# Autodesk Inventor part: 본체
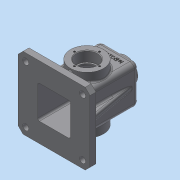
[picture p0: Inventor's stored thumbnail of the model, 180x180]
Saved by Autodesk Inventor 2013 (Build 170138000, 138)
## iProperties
Created: 2018-10
Part Number: 본체
Material: 일반
Document SubType Name: Modeling
Designer: Administrator
Density: 1 g/cm^3
Author: Administrator
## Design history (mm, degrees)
sketch "스케치1"
  geometry: L1 (32.5, 32.5)-(-32.5, 32.5); L2 (-32.5, 32.5)-(-32.5, -32.5); L3 (-32.5, -32.5)-(32.5, -32.5); L4 (32.5, -32.5)-(32.5, 32.5); L5 (32.5, 32.5)-(-32.5, -32.5); L6 (-32.5, 32.5)-(32.5, -32.5); 1 further point
  constraints: 12 end point, 2 midpoint, 2 parallel, 1 horizontal, 1 perpendicular
  dimensions: "d0" = 65 distance of L3.end L2.end; "d1" = 65 distance of L2.end L1.end
extrude "돌출1" new body sketch "스케치1" distance "d2" = 100; taper "d3" = 0 deg
node "작업 평면1"
sketch "스케치3"
  geometry: L1 (60, 60)-(-60, 60); L2 (-60, 60)-(-60, -60); L3 (-60, -60)-(60, -60); L4 (60, -60)-(60, 60); L5 (60, 60)-(-60, -60); L6 (-60, 60)-(60, -60); 3 further points
  constraints: 12 end point, 3 midpoint, 2 parallel, 1 coincident, 1 horizontal, 1 perpendicular
  dimensions: "d5" = 120 distance of L3.end L2.end; "d6" = 120 distance of L2.end L1.end
extrude "돌출2" join sketch "스케치3" distance "d7" = 10; taper "d8" = 0 deg
node "작업 평면2"
sketch "스케치16"
  geometry: C1 r 20 at (0, 0); 1 further point
  constraints: 1 centre point, 1 coincident
  dimensions: "d105" = 40 diameter of C1
extrude "돌출8" join sketch "스케치16" stored distance "d106" = 3; taper "d107" = 7 deg
sketch "스케치5"
  geometry: L1 (0, 0)-(0, -100) reference; L2 (92.5, -110)-(-27.5, -110) reference; C1 r 27.5 at (32.5, -55); 1 further point
  constraints: 1 centre point
  dimensions: "d12" = 55 diameter of C1; "d13" = 55 distance from line of L2 C1.centre; "d14" = 32.5 distance from line of C1.centre L1
extrude "돌출4" join sketch "스케치5" distance "d15" = 15; taper "d16" = 0 deg
sketch "스케치7"
  geometry: L1 (-27.5, -27.5)-(27.5, -27.5); L2 (27.5, -27.5)-(27.5, 27.5); L3 (27.5, 27.5)-(-27.5, 27.5); L4 (-27.5, 27.5)-(-27.5, -27.5); L5 (-27.5, -27.5)-(27.5, 27.5); L6 (27.5, -27.5)-(-27.5, 27.5); 1 further point
  constraints: 12 end point, 2 midpoint, 2 parallel, 1 horizontal, 1 perpendicular
  dimensions: "d17" = 55 distance of L3.end L2.end; "d18" = 55 distance of L2.end L1.end
extrude "돌출5" cut sketch "스케치7" distance "d19" = 105; taper "d20" = 0 deg
sketch "스케치8"
  geometry: C1 r 27.5 at (0, 0) reference; C2 r 17.5 at (0, 0); 1 further point
  constraints: 1 centre point, 1 coincident
  dimensions: "d21" = 35 diameter of C2
extrude "돌출6" cut sketch "스케치8" distance "d22" = 17; taper "d23" = 0 deg
sketch "스케치9"
  geometry: C1 r 17.5 at (0, 0) reference; C2 r 15 at (0, 0); 1 further point
  constraints: 1 centre point, 1 coincident
  dimensions: "d24" = 30 diameter of C2
extrude "돌출7" cut sketch "스케치9" distance "d25" = 3; taper "d26" = 0 deg
chamfer "모따기1" distance "d27" = 1; stored, may be unused: second distance "d28" = 2, angle "d29" = 45 deg
sketch "스케치10"
  geometry: L1 (-60, -100)-(-60, -110) reference; L2 (60, -100)-(-60, -100) reference; L3 (32.5, -100)-(60, -100) reference; L4 (60, -100)-(60, -110) reference; L5 (60, -110)-(27.5, -110) reference; L6 (27.5, -110)-(27.5, -5) reference; L7 (27.5, -5)-(-27.5, -5) reference; L8 (-27.5, -5)-(-27.5, -110) reference; L9 (-27.5, -110)-(-60, -110) reference; L10 (-60, -110)-(-60, -100) reference; L11 (-60, -100)-(-32.5, -100) reference; L12 (-32.5, -100)-(-32.5, 0) reference; L13 (-32.5, 0)-(-21.228, 0) reference; L14 (21.228, 0)-(32.5, 0) reference; L15 (32.5, 0)-(32.5, -100) reference; L16 (-48, -100)-(-38.544, -46.373); L17 (-21.228, 0)-(-20, 10) reference; L18 (-20, 10)-(20, 10) reference; L19 (20, 10)-(21.228, 0) reference; 1 further point
  constraints: 2 end point, 1 point on line
  dimensions: "d36" = 12 distance from line of L1 L16.start; "d37" = 10 deg angle of L1 L16
feature "리브1" sketch "스케치10" dims "d38" = 1, "d39" = 10, "d40" = 0, "d41" = 0, "d42" = 1, "d43" = 1
chamfer "모따기2" distance "d44" = 8; stored, may be unused: second distance "d45" = 2, angle "d46" = 45 deg
sketch "스케치12"
  geometry: L1 (-40, 27.5)-(-40, 30.5) reference; L2 (-40, 30.5)-(-37.5, 30.5) reference; L3 (-37.5, 30.5)-(-37.5, 46.5) reference; L4 (-37.5, 46.5)-(-36.5, 47.5) reference; L5 (-36.5, 47.5)-(-27.5, 47.5) reference; L6 (-27.5, 47.5)-(-27.5, 32.5) reference; L7 (-27.5, 32.5)-(0, 32.5) reference; L8 (0, 32.5)-(0, 21.228) reference; L9 (0, -21.228)-(0, -32.5) reference; L10 (0, -32.5)-(-27.5, -32.5) reference; L11 (-82.5, -47.5)-(-82.5, -32.5) reference; L12 (-72.5, -47.5)-(-82.5, -47.5) reference; L13 (-72.5, -30.5)-(-72.5, -47.5) reference; L14 (-37.5, -47.5)-(-37.5, -30.5) reference; L15 (-27.5, -47.5)-(-37.5, -47.5) reference; L16 (-27.5, -32.5)-(-27.5, -47.5) reference; L17 (-82.5, -32.5)-(-100, -32.5) reference; L18 (-100, -32.5)-(-100, -60) reference; L19 (-100, -60)-(-110, -60) reference; L20 (-110, -60)-(-110, -27.5) reference; L21 (-110, -27.5)-(-70, -27.5) reference; L22 (-5, -27.5)-(-5, 27.5) reference; L23 (-5, 27.5)-(-40, 27.5) reference; L24 (-70, 30.5)-(-70, 27.5) reference; L25 (-70, 27.5)-(-110, 27.5) reference; L26 (-110, 27.5)-(-110, 60) reference; L27 (-110, 60)-(-100, 60) reference; L28 (-100, 60)-(-100, 32.5) reference; L29 (-100, 32.5)-(-82.5, 32.5) reference; L30 (-82.5, 32.5)-(-82.5, 47.5) reference; L31 (-82.5, 47.5)-(-73.5, 47.5) reference; L32 (-73.5, 47.5)-(-72.5, 46.5) reference; L33 (-72.5, 46.5)-(-72.5, 30.5) reference; L34 (-72.5, 30.5)-(-70, 30.5) reference; L35 (-85.736, -42.5)-(-97.258, -42.5); L36 (-70, -27.5)-(-70, -30.5) reference; L37 (-70, -30.5)-(-72.5, -30.5) reference; L38 (-37.5, -30.5)-(-40, -30.5) reference; L39 (-40, -30.5)-(-40, -27.5) reference; L40 (-40, -27.5)-(-5, -27.5) reference; L41 (0, 21.228)-(10, 20) reference; L42 (10, 20)-(10, -20) reference; L43 (10, -20)-(0, -21.228) reference; 1 further point
  constraints: 2 end point, 1 parallel
  dimensions: "d47" = 15 distance between parallel lines of L35 L21
feature "리브2" sketch "스케치12" dims "d48" = 1, "d49" = 6, "d50" = 0, "d51" = 0, "d52" = 1, "d53" = 1
sketch "스케치13"
  geometry: L1 (52, 60)-(-52, 60) reference; L2 (-60, 52)-(-60, -52) reference; L3 (-52, -60)-(52, -60) reference; L4 (60, -52)-(60, 52) reference; 5 further points
  dimensions: "d54" = 95 distance of point (47.5, 47.5) point (-47.5, 47.5); "d56" = 95 distance of point (47.5, -47.5) point (47.5, 47.5); "d57" = 95 distance of point (-47.5, 47.5) point (-47.5, -47.5); "d58" = 12.5 distance from line of L3 point (47.5, -47.5); "d59" = 12.5 distance from line of L1 point (47.5, 47.5); "d60" = 12.5 distance from line of L3 point (-47.5, -47.5); "d61" = 12.5 distance from line of L2 point (-47.5, 47.5); "d62" = 12.5 distance from line of L4 point (47.5, 47.5)
hole "구멍1" sketch "스케치13" at (47.5, 47.5), (-47.5, 47.5), (-47.5, -47.5), (47.5, -47.5) diameter "d63" = 10; stored, may be unused: countersink angle "d67" = 90 deg, drill point angle "d69" = 0 deg; dims "d64" = 6, "d65" = 4, "d66" = 2, "d68" = 8
fillet "모깎기1" dims "d79" = 8
fillet "모깎기2" dims "d80" = 0.3
fillet "모깎기3" dims "d81" = 8
fillet "모깎기4" dims "d82" = 3
fillet "모깎기5" dims "d83" = 3
fillet "모깎기6" dims "d84" = 3
fillet "모깎기7" dims "d85" = 3
fillet "모깎기8" dims "d86" = 1
sketch "스케치14"
  geometry: L1 (84.5, -102)-(-35.5, -102) reference; L2 (-35.5, -102)-(-35.5, -92) reference; L3 (-35.5, -92)-(-4.123, -92) reference; L4 (0, -91)-(21.5, -91) reference; L5 (21.5, -91)-(21.5, -77.352) reference; L6 (0, 0)-(0, -28.834) reference; L7 (0, 0)-(49, 0) reference; L8 (49, 0)-(49, -28.834) reference; L9 (84.5, -92)-(84.5, -102) reference; L10 (53.123, -92)-(84.5, -92) reference; L11 (49, -65.166)-(49, -91) reference; L12 (0, -65.166)-(0, -91) reference; L13 (27.5, -91)-(49, -91) reference; L14 (27.5, -77.352)-(27.5, -91) reference; L15 (5.728, 18)-(43.272, 18) reference; L16 (-8, 0)-(-8, -91) reference; L17 (4.5, 18)-(44.5, 18) reference; C1 r 17.5 at (24.5, -47) reference; A1 r 30.5 centre (24.5, -47) between (0, -65.166) and (21.5, -77.352) reference; A2 r 30.5 centre (24.5, -47) between (49, -28.834) and (0, -28.834) reference; A3 r 30.5 centre (24.5, -47) between (27.5, -77.352) and (49, -65.166) reference; 2 further points
  constraints: 2 vertical alignment, 3 other
  dimensions: "d89" = 32.5 distance from line of L16 point (24.5, -8); "d108" = 26 distance from line of point (24.5, -8) L17
  node "절단 모서리 투영3"
sketch "스케치15" dims "d92" = 42
  geometry: C1 r 27.5 at (0, 0) reference; 3 further points
  constraints: 2 vertical alignment, 1 coincident, 2 other
hole "구멍3" sketch "스케치15" at (0, 21) diameter "d93" = 3.242; stored, may be unused: countersink angle "d97" = 90 deg, drill point angle "d99" = 118 deg; dims "d94" = 8, "d95" = 4, "d96" = 2, "d98" = 10
fillet "모깎기10" dims "d103" = 3
feature "엠보싱2" dims "d109" = 0.5, "d110" = 0
hole "구멍4" diameter "d113" = 22.835; stored, may be unused: countersink angle "d117" = 90 deg, drill point angle "d119" = 0 deg; dims "d111" = 10, "d112" = 10, "d114" = 50, "d115" = 4, "d116" = 2, "d118" = 10
fillet "모깎기11" dims "d120" = 3
chamfer "모따기3" distance "d121" = 1; stored, may be unused: second distance "d122" = 2, angle "d123" = 45 deg
node "솔리드1"
mirror "대칭1"
mirror "대칭2"
mirror "대칭3"
pattern_circular "원형 패턴1" dims angle "d101" = 360 deg
mirror "대칭4"
node "절단 모서리 투영1"
node "절단 모서리 투영2"
